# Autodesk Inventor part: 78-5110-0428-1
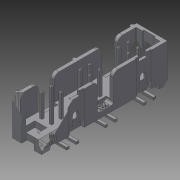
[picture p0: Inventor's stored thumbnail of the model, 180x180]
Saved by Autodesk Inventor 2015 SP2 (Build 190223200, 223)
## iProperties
Created: 2014-11
Part Number: 78-5110-0428-1
Material: Allgemein
Document SubType Name: Modeling
Designer: rYan
Density: 1 g/cm^3
Appearance: Vorgabe
Übersetzungsnorm: STEP AP203
Dateiname: 2520-6V0C-XX_STEP.stp
Vorprozessor: SIEMENS PLM Software NX 7.5
Postprozessor: Build: 200, Release: 2013 SP2 Update 1 - Date: Fri 06/14/2013
Gesendete Einheiten: Zoll
Unbestimmtheit: 0.002
Author: rYan
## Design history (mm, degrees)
node "78-5110-0428-11"
node "78-5110-0428-1-None"
node "Basis1"
